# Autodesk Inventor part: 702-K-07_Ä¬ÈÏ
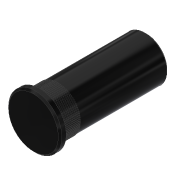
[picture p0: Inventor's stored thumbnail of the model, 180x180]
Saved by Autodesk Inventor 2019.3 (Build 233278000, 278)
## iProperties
Created: 2010-06
Part Number: 702-K-07_Ä¬ÈÏ
Material: Ogólny
Document SubType Name: Modeling
Designer: CADENGINEERING4
Density: 1 g/cm^3
Appearance: Gładki — czarny
Author: CADENGINEERING4
Revision Number: ÈÎºÎ
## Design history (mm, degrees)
feature "NONE"
node "Bryła1"
